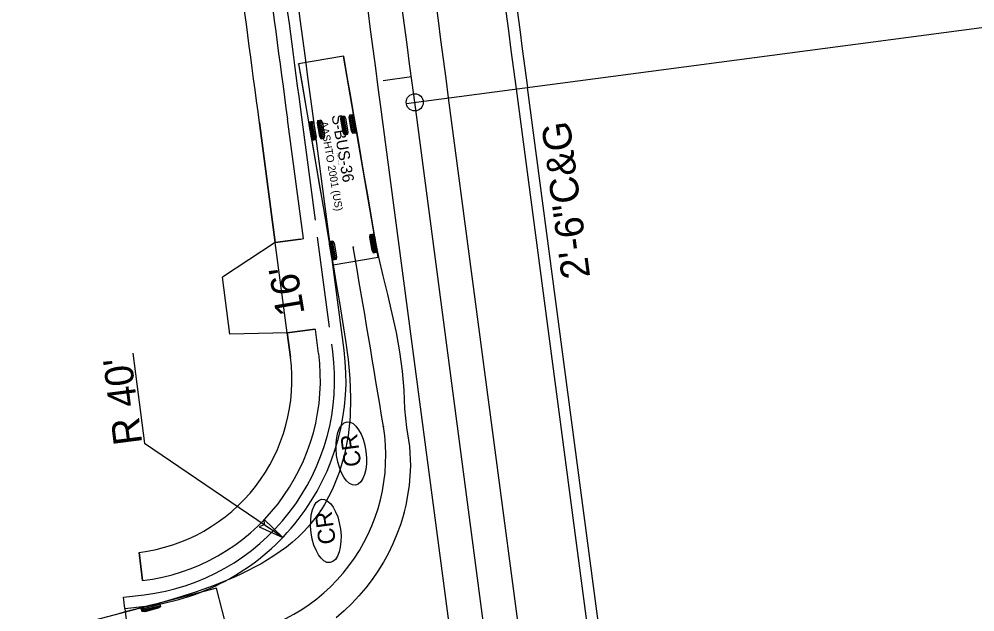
# Model space of a CAD drawing. Extents: x 2367848 to 2369479, y 800728 to 808616.
# Drawn here: x 2368486.7 to 2368654.5, y 806518.1 to 806622.2 of the extents above; entities that cross this region are included whole.
import ezdxf

# ---------------------------------------------------------------- set-up
doc = ezdxf.new("R2010")
doc.units = 0
for name, color, linetype in [('Prop AutoTurn Projected Path', 7, 'Continuous'), ('Prop AutoTurn Simulation', 7, 'Continuous'), ('Prop Conc 2ft 6in Curb and Gutter', 7, 'Continuous'), ('Prop Conc 4in Sidewalk', 7, 'Continuous'), ('Prop Conc Drive Radius Type', 7, 'Continuous'), ('Prop Conc Driveway', 7, 'Continuous'), ('Prop Dimension', 7, 'Continuous'), ('Prop EOT', 7, 'Continuous'), ('Prop Horizontal Alignment', 7, 'Continuous'), ('Prop Horizontal Alignment Station Label', 7, 'Continuous'), ('Prop Horizontal Alignment Tick Small', 7, 'Continuous'), ('Prop Lane Lines', 7, 'Continuous'), ('Prop Shade Light', 7, 'Continuous'), ('Prop Terminator CELL', 7, 'Continuous'), ('Prop WCC CELL', 7, 'Continuous'), ('Prop WCR CELL', 7, 'Continuous')]:
    doc.layers.add(name, color=color, linetype=linetype)

# ---------------------------------------------------------------- blocks, each defined once
blk = doc.blocks.new('CR')
at = {"layer": 'Prop WCC CELL'}
blk.add_ellipse((0.02, -0.02), major_axis=(5.61, 0), ratio=0.462467, dxfattribs=at)
blk.add_text('CR', height=3, dxfattribs=at).set_placement((-2.34, -1.5))

msp = doc.modelspace()

# ---------------------------------------------------------------- linework, layer by layer
at = {"layer": 'Prop AutoTurn Projected Path'}
for centre, radius, start, end in [((2364614.09, 805905.9), 3989, 9.3013, 9.76089), ((2368519.07, 806545.46), 32, 276.5258, 9.3013)]:
    msp.add_arc(centre, radius, start, end, dxfattribs=at)
at = {"layer": 'Prop AutoTurn Simulation'}
for p, q in [((2368543.64, 806615.68), (2368535.76, 806614.32)), ((2368535.76, 806614.32), (2368541.83, 806579.04)), ((2368549.71, 806580.4), (2368543.64, 806615.68)), ((2368538.28, 806600.89), (2368537.72, 806604.18)), ((2368538.49, 806600.93), (2368537.92, 806604.21)), ((2368538.69, 806600.96), (2368538.13, 806604.25)), ((2368539.76, 806601.15), (2368539.2, 806604.43)), ((2368539.97, 806601.18), (2368539.4, 806604.47)), ((2368540.17, 806601.22), (2368539.61, 806604.5)), ((2368543.87, 806601.85), (2368543.3, 806605.14)), ((2368544.07, 806601.89), (2368543.51, 806605.17)), ((2368544.28, 806601.92), (2368543.71, 806605.21)), ((2368545.35, 806602.11), (2368544.78, 806605.39)), ((2368545.55, 806602.14), (2368544.99, 806605.43)), ((2368545.76, 806602.18), (2368545.19, 806605.46)), ((2368548.96, 806581.11), (2368548.39, 806584.4)), ((2368549.16, 806581.15), (2368548.6, 806584.44)), ((2368549.37, 806581.19), (2368548.8, 806584.47)), ((2368541.89, 806579.9), (2368541.33, 806583.18)), ((2368542.1, 806579.93), (2368541.53, 806583.22)), ((2368542.3, 806579.97), (2368541.74, 806583.26)), ((2368541.83, 806579.04), (2368549.71, 806580.4)), ((2368549.71, 806580.4), (2368549.71, 806580.4)), ((2368521.32, 806522.25), (2368486.69, 806513.17)), ((2368523.35, 806514.51), (2368521.32, 806522.25)), ((2368508.16, 806518.58), (2368511.38, 806519.43)), ((2368508.21, 806518.38), (2368511.43, 806519.23)), ((2368508.26, 806518.18), (2368511.49, 806519.03))]:
    msp.add_line(p, q, dxfattribs=at)
for points in [[(2368535.76, 806614.32), (2368536.37, 806610.8), (2368536.97, 806607.27), (2368537.58, 806603.74), (2368538.19, 806600.21), (2368538.79, 806596.68), (2368539.4, 806593.16), (2368540.01, 806589.63), (2368540.61, 806586.1), (2368541.21, 806582.57), (2368541.81, 806579.04), (2368541.81, 806579.04), (2368541.81, 806579.04), (2368542.37, 806575.72), (2368542.93, 806572.4), (2368543.49, 806569.08), (2368544.01, 806565.75), (2368544.44, 806562.41), (2368544.75, 806559.06), (2368544.88, 806555.7), (2368544.79, 806552.34), (2368544.45, 806548.99), (2368543.82, 806545.71), (2368542.91, 806542.58), (2368541.73, 806539.64), (2368540.29, 806536.93), (2368539.65, 806535.91)], [(2368543.64, 806615.68), (2368544.25, 806612.15), (2368544.86, 806608.63), (2368545.47, 806605.1), (2368546.08, 806601.57), (2368546.69, 806598.04), (2368547.29, 806594.51), (2368547.9, 806590.98), (2368548.5, 806587.46), (2368549.11, 806583.93), (2368549.8, 806580.41), (2368549.8, 806580.41), (2368550.56, 806577.12), (2368551.37, 806573.82), (2368552.15, 806570.5), (2368552.87, 806567.15), (2368553.48, 806563.78), (2368553.95, 806560.39), (2368554.25, 806557.04), (2368554.38, 806553.76), (2368554.73, 806550.49), (2368555.23, 806547.16), (2368555.39, 806543.76), (2368555.18, 806540.3), (2368554.6, 806536.83), (2368554.26, 806535.45)], [(2368539.65, 806535.91), (2368539.48, 806535.66), (2368538.62, 806534.46), (2368537.7, 806533.32), (2368536.74, 806532.26), (2368535.74, 806531.26), (2368534.7, 806530.33), (2368533.62, 806529.47), (2368532.53, 806528.67), (2368531.42, 806527.92), (2368530.3, 806527.21), (2368529.17, 806526.55), (2368528.04, 806525.93), (2368526.9, 806525.34), (2368525.76, 806524.79), (2368524.62, 806524.26), (2368523.49, 806523.77), (2368522.35, 806523.29), (2368521.22, 806522.85), (2368520.09, 806522.42), (2368518.96, 806522.01), (2368517.83, 806521.62), (2368516.71, 806521.25), (2368515.59, 806520.89), (2368514.48, 806520.54), (2368513.33, 806520.21), (2368512.14, 806519.86), (2368510.9, 806519.52), (2368509.61, 806519.18), (2368508.29, 806518.83), (2368506.93, 806518.48), (2368505.55, 806518.12), (2368504.14, 806517.75)], [(2368554.26, 806535.45), (2368554.17, 806535.11), (2368553.64, 806533.4), (2368553.03, 806531.71), (2368552.33, 806530.05), (2368551.54, 806528.42), (2368550.66, 806526.82), (2368549.7, 806525.26), (2368548.66, 806523.76), (2368547.54, 806522.3), (2368546.35, 806520.89), (2368545.08, 806519.55), (2368543.74, 806518.27), (2368542.33, 806517.05)]]:
    msp.add_lwpolyline(points, dxfattribs=at)
for points in [[(2368538.74, 806600.97), (2368538.23, 806600.88), (2368538, 806601.32), (2368537.59, 806603.68), (2368537.67, 806604.17), (2368538.18, 806604.26), (2368538.41, 806603.82), (2368538.82, 806601.46)], [(2368540.22, 806601.22), (2368539.71, 806601.14), (2368539.48, 806601.57), (2368539.07, 806603.94), (2368539.14, 806604.42), (2368539.66, 806604.51), (2368539.89, 806604.08), (2368540.3, 806601.71)], [(2368544.33, 806601.93), (2368543.82, 806601.84), (2368543.58, 806602.28), (2368543.18, 806604.64), (2368543.25, 806605.13), (2368543.76, 806605.22), (2368544, 806604.78), (2368544.4, 806602.42)], [(2368545.81, 806602.19), (2368545.29, 806602.1), (2368545.06, 806602.53), (2368544.65, 806604.9), (2368544.73, 806605.38), (2368545.24, 806605.47), (2368545.48, 806605.04), (2368545.88, 806602.67)], [(2368549.42, 806581.19), (2368548.91, 806581.11), (2368548.67, 806581.54), (2368548.27, 806583.9), (2368548.34, 806584.39), (2368548.85, 806584.48), (2368549.09, 806584.05), (2368549.49, 806581.68)], [(2368542.36, 806579.98), (2368541.84, 806579.89), (2368541.61, 806580.32), (2368541.2, 806582.69), (2368541.28, 806583.18), (2368541.79, 806583.26), (2368542.02, 806582.83), (2368542.43, 806580.47)], [(2368508.27, 806518.13), (2368508.14, 806518.63), (2368508.55, 806518.9), (2368510.88, 806519.51), (2368511.37, 806519.48), (2368511.5, 806518.98), (2368511.09, 806518.71), (2368508.77, 806518.1)]]:
    msp.add_lwpolyline(points, close=True, dxfattribs=at)
for centre in [(2368535.76, 806614.32), (2368543.64, 806615.68), (2368545.35, 806582.18), (2368550.65, 806550.63), (2368550.65, 806550.63), (2368539.65, 806535.91), (2368539.65, 806535.91), (2368554.26, 806535.45), (2368554.26, 806535.45)]:
    msp.add_circle(centre, 0.0417, dxfattribs=at)
at = {"layer": 'Prop Conc 2ft 6in Curb and Gutter'}
for p, q in [((2368604.81, 806391.98), (2368575.97, 806610.21)), ((2368538.71, 806586.91), (2368536.32, 806604.97)), ((2368541.76, 806563.79), (2368541.59, 806565.1)), ((2368505.02, 806520.65), (2368508.65, 806521.09)), ((2368505.26, 806518.67), (2368505.02, 806520.65))]:
    msp.add_line(p, q, dxfattribs=at)
for centre, radius, start, end in [((2345971.56, 803623.74), 22800.85, 7.526261, 7.801711), ((2345971.56, 803623.74), 22760.85, 7.526261, 7.675139), ((2368504.09, 806558.82), 38, 276.8992, 7.5263)]:
    msp.add_arc(centre, radius, start, end, dxfattribs=at)
at = {"layer": 'Prop Conc 4in Sidewalk'}
for p, q in [((2368536.61, 806583.65), (2368533.84, 806604.64)), ((2368531.66, 806582.95), (2368528.88, 806603.99)), ((2368539.28, 806563.47), (2368538.72, 806567.7)), ((2368534.32, 806562.81), (2368533.76, 806567.09)), ((2368508.35, 806523.57), (2368507.75, 806528.54))]:
    msp.add_line(p, q, dxfattribs=at)
for centre, radius, start, end in [((2345971.56, 803623.74), 22753.35, 7.526261, 7.682685), ((2345971.56, 803623.74), 22758.35, 7.526261, 7.682583), ((2368535.73, 806586.52), 3, 277.5698, 287.1738), ((2368538.6, 806564.69), 3.01, 87.742, 97.3082), ((2368504.09, 806558.82), 30.5, 276.8992, 7.5263), ((2368504.09, 806558.82), 35.5, 276.8992, 7.5263)]:
    msp.add_arc(centre, radius, start, end, dxfattribs=at)
at = {"layer": 'Prop Conc Drive Radius Type'}
msp.add_line((2368541.19, 806568.07), (2368539.1, 806583.93), dxfattribs=at)
at = {"layer": 'Prop Conc Driveway'}
for p, q in [((2368531.66, 806582.95), (2368522.38, 806576.86)), ((2368536.12, 806583.54), (2368531.66, 806582.95)), ((2368533.76, 806567.09), (2368531.66, 806582.95)), ((2368523.7, 806566.89), (2368522.38, 806576.86)), ((2368533.76, 806567.09), (2368538.22, 806567.68)), ((2368533.76, 806567.09), (2368523.7, 806566.89))]:
    msp.add_line(p, q, dxfattribs=at)
at = {"layer": 'Prop Dimension'}
for p in [(2368506.67, 806563.5), (2368532.98, 806531.15)]:
    msp.add_line(p, (2368508.71, 806547.63), dxfattribs=at)
at = {"layer": 'Prop EOT'}
for p, q in [((2368602.82, 806391.71), (2368573.99, 806609.95)), ((2368543.74, 806564.06), (2368538.3, 806605.23)), ((2368505.26, 806518.67), (2368508.89, 806519.11)), ((2368505.26, 806518.67), (2368508.05, 806494.27))]:
    msp.add_line(p, q, dxfattribs=at)
for centre, radius, start, end in [((2345971.56, 803623.74), 22798.85, 7.526261, 7.801711), ((2345971.56, 803623.74), 22762.85, 7.526261, 7.801711), ((2368504.09, 806558.82), 40, 276.8992, 7.5263)]:
    msp.add_arc(centre, radius, start, end, dxfattribs=at)
at = {"layer": 'Prop Horizontal Alignment'}
msp.add_line((2368631.17, 806039.71), (2368556.15, 806607.59), dxfattribs=at)
msp.add_arc((2345971.56, 803623.74), 22780.85, 7.526261, 7.801711, dxfattribs=at)
at = {"layer": 'Prop Horizontal Alignment Station Label'}
msp.add_line((2368554.66, 806607.39), (2368766.24, 806635.35), dxfattribs=at)
msp.add_circle((2368556.15, 806607.59), 1.5, dxfattribs=at)
at = {"layer": 'Prop Horizontal Alignment Tick Small'}
msp.add_line((2368555.56, 806612.04), (2368550.6, 806611.38), dxfattribs=at)
at = {"layer": 'Prop Lane Lines'}
for p, q in [((2368637.12, 806040.49), (2368562.1, 806608.37)), ((2368625.23, 806038.92), (2368550.2, 806606.8))]:
    msp.add_line(p, q, dxfattribs=at)
for radius in [22786.85, 22774.85]:
    msp.add_arc((2345971.56, 803623.74), radius, 7.526261, 7.801711, dxfattribs=at)
at = {"layer": 'Prop Shade Light'}
for p, q in [((2368536.61, 806583.65), (2368533.84, 806604.64)), ((2368528.88, 806603.99), (2368531.66, 806582.95)), ((2368531.66, 806582.95), (2368536.12, 806583.54)), ((2368538.22, 806567.68), (2368533.76, 806567.09)), ((2368539.28, 806563.47), (2368538.72, 806567.7)), ((2368533.76, 806567.09), (2368534.32, 806562.81)), ((2368507.75, 806528.54), (2368508.35, 806523.57))]:
    msp.add_line(p, q, dxfattribs=at)
for centre, radius, start, end in [((2345971.56, 803623.74), 22753.35, 7.526261, 7.682685), ((2345971.56, 803623.74), 22758.35, 7.526261, 7.682583), ((2368535.73, 806586.52), 3, 277.5698, 287.1738), ((2368538.6, 806564.69), 3.01, 87.742, 97.3082), ((2368504.09, 806558.82), 30.5, 276.8992, 7.5263), ((2368504.09, 806558.82), 35.5, 276.8992, 7.5263)]:
    msp.add_arc(centre, radius, start, end, dxfattribs=at)
at = {"layer": 'Prop Terminator CELL'}
msp.add_lwpolyline([(2368528.82, 806533.04), (2368532.98, 806531.15), (2368529.68, 806534.36), (2368529.71, 806533.37)], close=True, dxfattribs=at)

# ---------------------------------------------------------------- block references
at = {"layer": 'Prop WCR CELL', "rotation": 97.54241161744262}
for p in [(2368544.99, 806545.89), (2368540.52, 806532.27)]:
    msp.add_blockref('CR', p, dxfattribs=at)

# ---------------------------------------------------------------- texts
at = {"layer": 'Prop AutoTurn Simulation'}
for s, height, p in [('AASHTO 2001 (US)', 1.3333, (2368539.54, 806604.13)), ('S-BUS-36', 2, (2368541.54, 806605.27)), ('(c) 2014 Transoft Solutions, Inc. All rights reserved.', 0.08, (2368542.42, 806598.96))]:
    msp.add_text(s, height=height, rotation=279.7609, dxfattribs=at).set_placement(p)
at = {"layer": 'Prop Dimension'}
for s, rotation, p in [('2\'-6"C&G', 97.5241, (2368586.96, 806576.93)), ("16'", 99.6019, (2368536.84, 806570.52)), ("R 40'", 97.3111, (2368508.32, 806547.71))]:
    msp.add_text(s, height=5, rotation=rotation, dxfattribs=at).set_placement(p)

doc.saveas('drawing.dxf')
